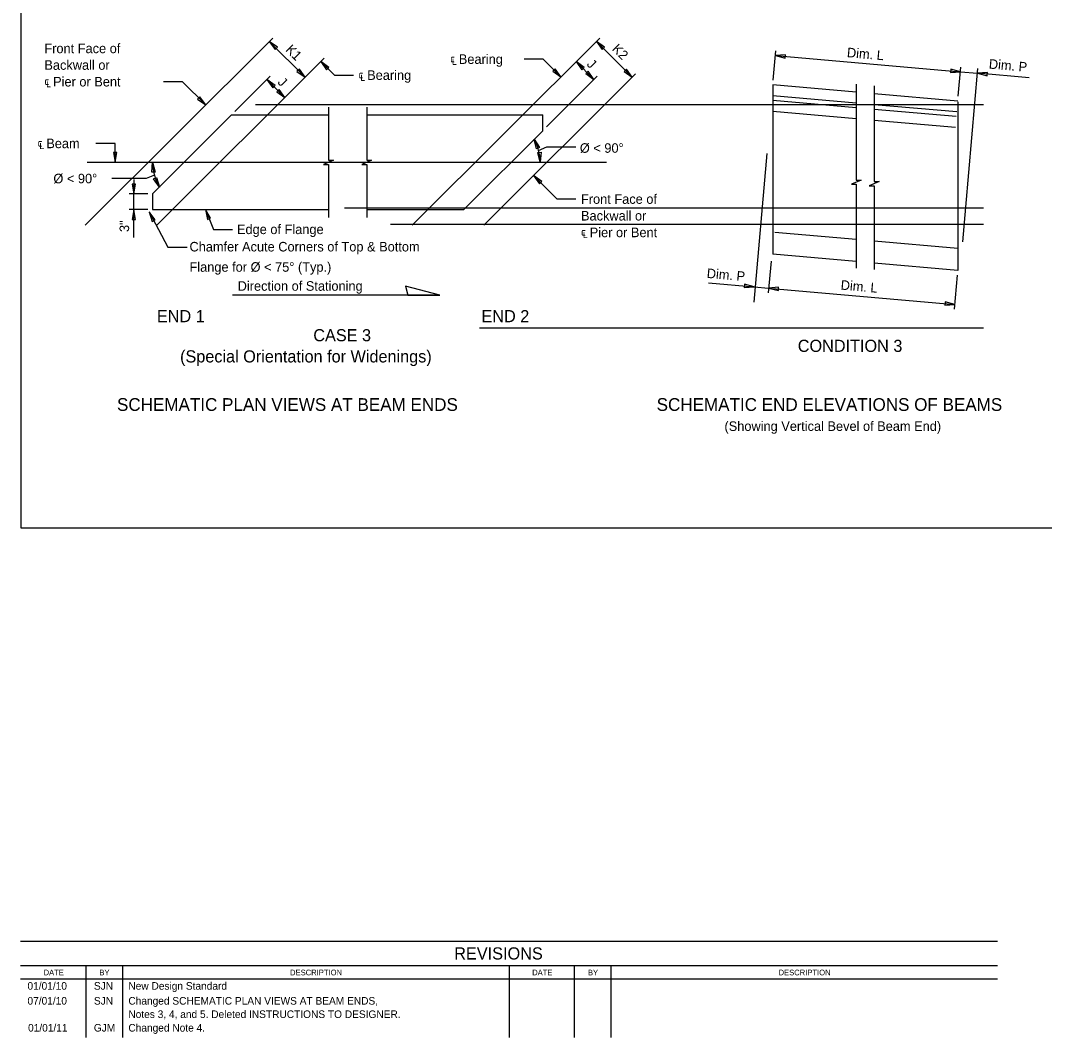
# Model space of a CAD drawing. Extents: x -119 to 80, y -12 to 144.
# Drawn here: x -12.04 to 4.16, y 31.76 to 47.86 of the extents above; entities that cross this region are included whole.
import ezdxf

# ---------------------------------------------------------------- set-up
doc = ezdxf.new("R2010")
doc.units = 0
for name, color, linetype in [('ActivePts-ConstElements', 7, 'Continuous'), ('AdhocPoint_dp', 7, 'Continuous'), ('Border', 7, 'Continuous'), ('CL_Major', 7, 'Continuous'), ('Patterning', 7, 'Continuous'), ('SheetLines_dp', 7, 'Continuous'), ('TextMisc', 7, 'Continuous')]:
    doc.layers.add(name, color=color, linetype=linetype)

msp = doc.modelspace()

# ---------------------------------------------------------------- linework, layer by layer
at = {"layer": 'ActivePts-ConstElements'}
msp.add_lwpolyline([(-12.032, 59.628), (18.768, 59.628), (18.768, 39.828), (-12.032, 39.828)], close=True, dxfattribs=at)
at = {"layer": 'AdhocPoint_dp'}
for p, q in [((-8.107, 47.532), (-7.541, 46.965)), ((-2.932, 47.532), (-2.366, 46.965)), ((-0.134, 46.92), (-0.094, 47.383)), ((-7.292, 47.213), (-7.078, 46.998)), ((-3.774, 47.252), (-4.076, 47.252)), ((-3.493, 46.971), (-3.774, 47.252)), ((-2.971, 46.93), (-3.253, 47.212)), ((-0.1, 47.308), (2.828, 47.051)), ((-7.078, 46.998), (-6.776, 46.998)), ((2.794, 46.664), (2.834, 47.127)), ((2.828, 47.051), (3.096, 47.028)), ((2.863, 44.36), (3.103, 47.103)), ((3.914, 46.956), (3.096, 47.028)), ((-9.479, 46.895), (-9.782, 46.895)), ((-9.113, 46.528), (-9.479, 46.895)), ((-8.652, 46.422), (-8.092, 46.982)), ((-8.145, 46.929), (-7.861, 46.644)), ((-3.72, 46.182), (-2.918, 46.983)), ((-10.548, 45.917), (-10.85, 45.917)), ((-10.546, 45.619), (-10.548, 45.917)), ((-0.236, 45.758), (-0.442, 43.405)), ((-3.927, 45.407), (-3.56, 45.04)), ((-10.249, 45.345), (-10.249, 45.119)), ((-10.031, 45.119), (-10.325, 45.119)), ((-10.249, 44.869), (-10.249, 45.119)), ((-3.56, 45.04), (-3.257, 45.04)), ((-10.031, 44.869), (-10.325, 44.869)), ((-10.249, 44.428), (-10.249, 44.869)), ((-10.008, 44.833), (-9.714, 44.274)), ((-9.119, 44.869), (-8.99, 44.557)), ((-8.99, 44.557), (-8.687, 44.557)), ((-9.714, 44.274), (-9.409, 44.274)), ((-0.169, 44.053), (-0.213, 43.552)), ((2.777, 43.831), (2.73, 43.295)), ((-1.157, 43.71), (-0.435, 43.647)), ((-0.435, 43.647), (-0.207, 43.627)), ((-0.207, 43.627), (2.737, 43.37)), ((-5.411, 43.514), (-8.687, 43.514))]:
    msp.add_line(p, q, dxfattribs=at)
for points in [[(-8.107, 47.532), (-8.016, 47.403), (-7.978, 47.44)], [(-2.932, 47.532), (-2.841, 47.403), (-2.803, 47.44)], [(-0.1, 47.308), (0.053, 47.268), (0.057, 47.32)], [(-7.292, 47.213), (-7.201, 47.084), (-7.163, 47.121)], [(-3.253, 47.212), (-3.161, 47.083), (-3.124, 47.12)], [(-7.541, 46.965), (-7.632, 47.094), (-7.67, 47.057)], [(-3.493, 46.971), (-3.585, 47.1), (-3.622, 47.063)], [(-2.971, 46.93), (-3.063, 47.059), (-3.1, 47.022)], [(-2.366, 46.965), (-2.458, 47.094), (-2.495, 47.057)], [(2.828, 47.051), (2.674, 47.091), (2.67, 47.039)], [(3.096, 47.028), (3.249, 46.988), (3.254, 47.041)], [(-8.145, 46.929), (-8.054, 46.799), (-8.016, 46.837)], [(-7.861, 46.644), (-7.953, 46.773), (-7.99, 46.736)], [(-9.113, 46.528), (-9.205, 46.657), (-9.242, 46.62)], [(-3.915, 45.986), (-3.83, 45.853), (-3.879, 45.832)], [(-10.546, 45.619), (-10.521, 45.775), (-10.573, 45.775)], [(-3.822, 45.619), (-3.86, 45.773), (-3.807, 45.777)], [(-9.953, 45.619), (-9.915, 45.465), (-9.968, 45.461)], [(-9.847, 45.227), (-9.938, 45.357), (-9.89, 45.38)], [(-3.927, 45.407), (-3.835, 45.278), (-3.797, 45.315)], [(-10.249, 45.119), (-10.223, 45.275), (-10.276, 45.275)], [(-10.249, 44.869), (-10.276, 44.713), (-10.223, 44.713)], [(-10.008, 44.833), (-9.959, 44.683), (-9.912, 44.707)], [(-9.119, 44.869), (-9.084, 44.714), (-9.035, 44.735)], [(-0.435, 43.647), (-0.589, 43.687), (-0.593, 43.635)], [(-0.207, 43.627), (-0.053, 43.587), (-0.049, 43.64)], [(2.737, 43.37), (2.584, 43.41), (2.579, 43.357)]]:
    msp.add_lwpolyline(points, close=True, dxfattribs=at)
for points in [[(1.18, 46.854), (1.18, 45.338), (1.258, 45.338), (1.103, 45.271), (1.18, 45.271), (1.18, 43.941)], [(1.463, 46.829), (1.463, 45.314), (1.54, 45.314), (1.385, 45.246), (1.463, 45.246), (1.463, 43.919)], [(-7.171, 46.494), (-7.171, 45.653), (-7.094, 45.653), (-7.249, 45.585), (-7.171, 45.585), (-7.171, 44.744)], [(-6.566, 46.494), (-6.566, 45.653), (-6.489, 45.653), (-6.644, 45.585), (-6.566, 45.585), (-6.566, 44.744)], [(-3.846, 45.808), (-3.716, 45.862), (-3.255, 45.862)], [(-9.926, 45.416), (-10.056, 45.362), (-10.599, 45.362)]]:
    msp.add_lwpolyline(points, dxfattribs=at)
for centre, start, end in [((-4.597, 45.619), 0, 28.3225), ((-9.179, 45.619), 180, 210.3691)]:
    msp.add_arc(centre, 0.774, start, end, dxfattribs=at)
at = {"layer": 'Border'}
for p, q in [((3.415, 33.285), (-12.044, 33.285)), ((3.415, 32.899), (-12.044, 32.899)), ((-11.011, 32.899), (-11.011, 31.763)), ((-10.431, 32.899), (-10.431, 31.763)), ((-4.314, 32.899), (-4.314, 31.763)), ((-3.282, 32.899), (-3.282, 31.763)), ((-2.702, 32.899), (-2.702, 31.763)), ((-12.044, 32.694), (3.415, 32.694))]:
    msp.add_line(p, q, dxfattribs=at)
at = {"layer": 'CL_Major'}
for p, q in [((-8.054, 47.585), (-11.021, 44.623)), ((-5.846, 44.623), (-2.877, 47.585)), ((-7.239, 47.266), (-9.888, 44.623)), ((-4.712, 44.623), (-2.312, 47.018)), ((-10.987, 45.619), (-2.775, 45.619))]:
    msp.add_line(p, q, dxfattribs=at)
at = {"layer": 'Patterning'}
for p, q in [((-0.141, 46.845), (-0.141, 44.162)), ((1.18, 46.729), (-0.141, 46.845)), ((1.18, 46.555), (-0.141, 46.671)), ((2.784, 46.589), (1.463, 46.704)), ((1.18, 46.481), (-0.141, 46.596)), ((2.769, 46.416), (1.463, 46.53)), ((2.784, 46.576), (2.784, 43.906)), ((-8.705, 46.369), (-9.955, 45.119)), ((-8.705, 46.369), (-7.171, 46.369)), ((-6.566, 46.369), (-3.782, 46.369)), ((-3.782, 46.119), (-3.782, 46.369)), ((1.18, 46.307), (-0.141, 46.422)), ((2.762, 46.342), (1.463, 46.456)), ((2.747, 46.17), (1.463, 46.282)), ((-5.032, 44.869), (-3.782, 46.119)), ((-9.955, 45.119), (-9.955, 44.869)), ((-9.955, 44.869), (-7.171, 44.869)), ((-6.566, 44.869), (-5.032, 44.869)), ((1.18, 44.394), (-0.111, 44.507)), ((2.784, 44.254), (1.463, 44.369)), ((1.18, 44.047), (-0.141, 44.162)), ((2.784, 43.906), (1.463, 44.022))]:
    msp.add_line(p, q, dxfattribs=at)
at = {"layer": 'SheetLines_dp'}
for p, q in [((-8.325, 46.534), (3.194, 46.534)), ((3.194, 44.893), (-6.919, 44.893)), ((3.194, 44.633), (-6.19, 44.633)), ((3.194, 42.992), (-4.784, 42.992))]:
    msp.add_line(p, q, dxfattribs=at)
at = {"layer": 'TextMisc'}
msp.add_lwpolyline([(-5.954, 43.657), (-5.918, 43.514), (-5.411, 43.514)], close=True, dxfattribs=at)

# ---------------------------------------------------------------- texts
for s, height, p in [('Front Face of', 0.1512, (-11.666, 47.346)), ('℄ Bearing', 0.1512, (-5.247, 47.176)), ('Backwall or', 0.1512, (-11.666, 47.083)), ('℄ Bearing', 0.1512, (-6.697, 46.923)), ('℄ Pier or Bent', 0.1512, (-11.666, 46.819)), ('℄ Beam', 0.1512, (-11.774, 45.842)), ('Ø < 90°', 0.1512, (-3.194, 45.769)), ('Ø < 90°', 0.1512, (-11.523, 45.286)), ('Front Face of', 0.1512, (-3.176, 44.961)), ('Backwall or', 0.1512, (-3.176, 44.697)), ('Edge of Flange', 0.1512, (-8.619, 44.482)), ('℄ Pier or Bent', 0.1512, (-3.176, 44.433)), ('Chamfer Acute Corners of Top & Bottom ', 0.1512, (-9.37, 44.207)), ('Flange for Ø < 75° (Typ.)', 0.1512, (-9.37, 43.886)), ('Direction of Stationing', 0.1512, (-8.608, 43.585)), ('END 1', 0.192, (-9.885, 43.087)), ('END 2', 0.192, (-4.75, 43.087)), ('CASE 3', 0.192, (-7.411, 42.785)), ('CONDITION 3', 0.192, (0.254, 42.617)), ('(Special Orientation for Widenings)', 0.192, (-9.519, 42.45)), ('SCHEMATIC PLAN VIEWS AT BEAM ENDS', 0.2016, (-10.517, 41.683)), ('SCHEMATIC END ELEVATIONS OF BEAMS', 0.2016, (-1.979, 41.683)), ('(Showing Vertical Bevel of Beam End)', 0.1512, (-0.906, 41.366)), ('REVISIONS', 0.1925, (-5.182, 32.998)), ('BY', 0.0901, (-10.796, 32.747)), ('BY', 0.0901, (-3.066, 32.747)), ('01/01/10', 0.12, (-11.933, 32.52)), ('SJN', 0.12, (-10.882, 32.52)), ('New Design Standard', 0.12, (-10.337, 32.52)), ('07/01/10', 0.12, (-11.933, 32.284)), ('SJN', 0.12, (-10.882, 32.284)), ('Changed SCHEMATIC PLAN VIEWS AT BEAM ENDS,', 0.12, (-10.337, 32.284)), ('Notes 3, 4, and 5. Deleted INSTRUCTIONS TO DESIGNER.', 0.12, (-10.337, 32.072)), ('01/01/11', 0.12, (-11.924, 31.857)), ('GJM', 0.12, (-10.883, 31.857)), ('Changed Note 4.', 0.12, (-10.337, 31.857))]:
    msp.add_text(s, height=height, dxfattribs=at).set_placement(p)
for s, height, rotation, p in [('K1', 0.1512, 314.9945, (-7.86, 47.392)), ('K2', 0.1512, 314.9945, (-2.695, 47.401)), ('Dim. L', 0.1512, 355.0003, (1.027, 47.285)), ('J', 0.151, 314.9945, (-3.095, 47.161)), ('Dim. P', 0.1512, 355.0003, (3.272, 47.103)), ('J', 0.151, 314.9945, (-7.986, 46.876)), ('3"', 0.1512, 90, (-10.325, 44.515)), ('Dim. P', 0.1512, 355.0003, (-1.191, 43.789)), ('Dim. L', 0.1512, 355.0003, (0.928, 43.604)), ('DATE', 0.0897, 359.8693, (-11.678, 32.748)), ('DESCRIPTION', 0.09005, 0.0498, (-7.779, 32.747)), ('DATE', 0.0897, 359.8693, (-3.948, 32.748)), ('DESCRIPTION', 0.09005, 0.0498, (-0.05, 32.747))]:
    msp.add_text(s, height=height, rotation=rotation, dxfattribs=at).set_placement(p)

doc.saveas('drawing.dxf')
